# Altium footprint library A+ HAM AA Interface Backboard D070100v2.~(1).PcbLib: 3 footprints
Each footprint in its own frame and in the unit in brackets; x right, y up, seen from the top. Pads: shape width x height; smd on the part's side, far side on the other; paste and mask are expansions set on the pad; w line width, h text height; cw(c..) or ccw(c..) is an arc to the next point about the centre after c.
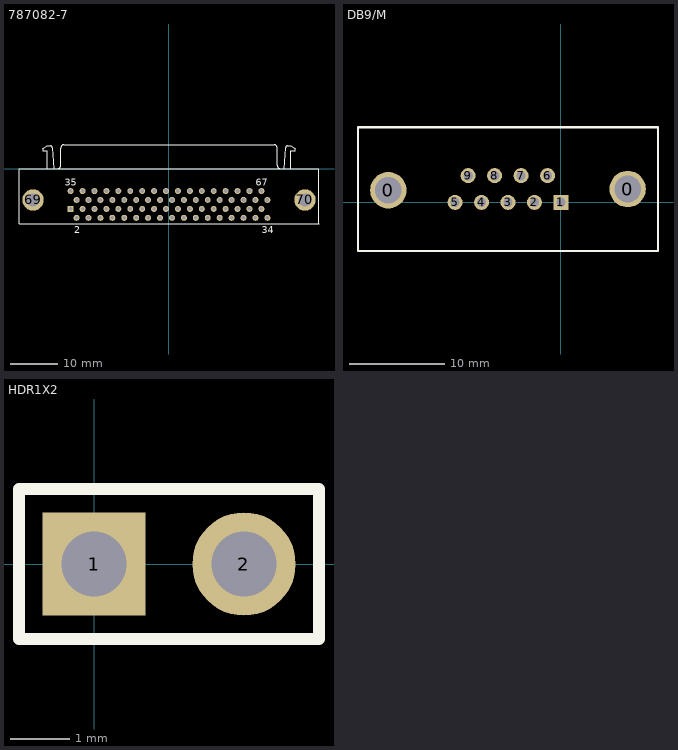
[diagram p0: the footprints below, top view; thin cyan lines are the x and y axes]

## 787082-7 [mm] "Connector; D Subminiature 050 Series; 68 Position; Right Angle"
height 10.44
pads (70):
  rect 1.27x1.27 hole 0.762: 1(-20.955,-8.555)
  round 1.27 hole 0.762: 2(-19.685,-10.46) 3(-18.415,-8.555) 4(-17.145,-10.46) 5(-15.875,-8.555) 6(-14.605,-10.46) 7(-13.335,-8.555) 8(-12.065,-10.46) 9(-10.795,-8.555) 10(-9.525,-10.46) 11(-8.255,-8.555) 12(-6.985,-10.46) 13(-5.715,-8.555) 14(-4.445,-10.46) 15(-3.175,-8.555) 16(-1.905,-10.46) 17(-0.635,-8.555) 18(0.635,-10.46) 19(1.905,-8.555) 20(3.175,-10.46) 21(4.445,-8.555) 22(5.715,-10.46) 23(6.985,-8.555) 24(8.255,-10.46) 25(9.525,-8.555) 26(10.795,-10.46) 27(12.065,-8.555) 28(13.335,-10.46) 29(14.605,-8.555) 30(15.875,-10.46) 31(17.145,-8.555) 32(18.415,-10.46) 33(19.685,-8.555) 34(20.955,-10.46) 35(-20.955,-4.745) 36(-19.685,-6.65) 37(-18.415,-4.745) 38(-17.145,-6.65) 39(-15.875,-4.745) 40(-14.605,-6.65) 41(-13.335,-4.745) 42(-12.065,-6.65) 43(-10.795,-4.745) 44(-9.525,-6.65) 45(-8.255,-4.745) 46(-6.985,-6.65) 47(-5.715,-4.745) 48(-4.445,-6.65) 49(-3.175,-4.745) 50(-1.905,-6.65) 51(-0.635,-4.745) 52(0.635,-6.65) 53(1.905,-4.745) 54(3.175,-6.65) 55(4.445,-4.745) 56(5.715,-6.65) 57(6.985,-4.745) 58(8.255,-6.65) 59(9.525,-4.745) 60(10.795,-6.65) 61(12.065,-4.745) 62(13.335,-6.65) 63(14.605,-4.745) 64(15.875,-6.65) 65(17.145,-4.745) 66(18.415,-6.65) 67(19.685,-4.745) 68(20.955,-6.65)
  round 4.55 hole 2.77: 69(-28.955,-6.65) 70(28.955,-6.65)
Top Overlay:
  lines w0.2: -26.84,4.27 -25.9,4.898 -25.178,4.898 cw(c-25.28,4.5) -24.87,4.5 ; -26.826,4.255 ccw(c-26.6,4.01) -26.85,3.79 -25.97,3.79 -25.97,0 ; -24.87,4.52 -24.5,0 ; -23.76,0.005 ccw(c-23.76,0.7) -23.065,0.7 -23.065,4.4 cw(c-22.37,4.4) -22.37,5.095 ; -22.37,5.11 22.37,5.11 ; 22.37,5.095 cw(c22.37,4.4) 23.065,4.4 23.065,0.7 ccw(c23.76,0.7) 23.76,0.005 ; 24.5,0 24.87,4.52 ; 24.87,4.5 cw(c25.28,4.5) 25.178,4.898 25.9,4.898 26.84,4.27 ; 25.97,0 25.97,3.79 26.85,3.79 ccw(c26.6,4.01) 26.826,4.255 ; -31.95,-11.76 -31.95,0 31.95,0 31.95,-11.76 -31.95,-11.76
  text "35" at -22.205,-3.62 h1.5
  text "67" at 18.435,-3.62 h1.5
  text "34" at 19.705,-13.735 h1.5
  text "2" at -20.185,-13.735 h1.5
3D body "c-1-787082-7-v-3d.stp": height 9.51, standoff -3.8, extent -31.941,-11.786 31.941,5.08

## DB9/M [mil]
pads (11):
  round 150 hole 110: 0(-711,50) 0(275,55)
  rect 62x62 hole 38: 1(0,0)
  round 62 hole 38: 2(-109,0) 3(-218,0) 4(-327,0) 5(-436,0) 6(-55,110) 7(-164,110) 8(-273,110) 9(-382,110)
Top Overlay:
  lines w8: -836,310 -836,-200 400,-200
  lines w10: -836,310 400,310 400,-200
3D body "D9M (A34064-ND).stp": height 469.9, standoff -124.5, extent -827,-194 389,302

## HDR1X2 [mm] "Connector; Header; 2 Position"
height 6
pads (2):
  rect 1.75x1.75 hole 1.1: 1(0,0)
  round 1.75 hole 1.1: 2(2.54,0)
Top Overlay:
  lines w0.2: -1.27,-1.27 3.81,-1.27 3.81,1.27 -1.27,1.27 -1.27,-1.27
3D body "MOLEX 2pin 2.54mm (0022032021).STEP": height 10.8, standoff -3.42, extent -1.145,-1.194 3.685,1.146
